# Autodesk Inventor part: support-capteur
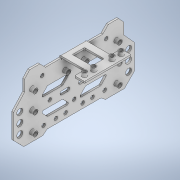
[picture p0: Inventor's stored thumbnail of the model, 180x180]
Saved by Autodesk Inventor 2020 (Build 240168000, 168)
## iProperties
Created: 2022-02
Part Number: support-capteur
Material: Générique
Document SubType Name: Modeling
Designer: bruno
Density: 1 g/cm^3
Appearance: Par défaut
Author: bruno
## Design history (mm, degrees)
sketch "Esquisse1"
  geometry: L1 (32.088, -75.124)-(29.483, 74.118); L2 (29.483, 74.118)-(111.566, 75.551); L3 (111.566, 75.551)-(114.171, -73.691); L4 (114.171, -73.691)-(32.088, -75.124); L5 (66.232, 46.839)-(46.199, 46.839); L6 (66.23, -52.161)-(46.2, -52.161); L7 (89.845, 25.399)-(89.845, 33.715); L8 (37.796, 38.782)-(37.796, 23.107); L9 (46.199, 46.839)-(37.796, 38.532); L10 (89.845, 25.399)-(85.193, 20.8); L11 (85.193, 20.8)-(85.193, -2.661); L12 (89.845, 33.715)-(85.193, 37.93); L13 (85.193, 37.93)-(76.064, 37.93); L14 (76.064, 37.93)-(66.232, 46.839); L15 (37.796, 23.107)-(40.701, 19.391); L16 (40.701, 19.391)-(40.701, -2.661); L17 (40.701, -2.661)-(50.092, -2.661); L18 (50.092, -2.661)-(85.193, -2.661); L19 (71.331, 18.786)-(71.331, 3.129); L20 (71.016, 19.515)-(66.917, 23.371); L21 (65.232, 7.141)-(65.232, 22.643); L22 (69.631, 2.414)-(65.532, 6.426); L23 (61.89, 7.414)-(61.89, 2.414); L24 (58.89, 7.414)-(58.89, 2.414); L25 (60.39, 17.308)-(60.39, 7.414); L26 (49.764, 19.515)-(53.863, 23.371); L27 (55.548, 7.141)-(55.548, 22.643); L28 (49.449, 18.786)-(49.449, 3.129); L29 (51.148, 2.414)-(55.247, 6.426); C1 r 1.5 at (80.628, 23.543); C2 r 2.5 at (64.046, 41.839); C3 r 2.5 at (56.046, 41.839); C4 r 2.5 at (48.046, 41.839); C5 r 1.5 at (60.39, 17.308); C6 r 1.5 at (44.701, 22.339); C7 r 1.5 at (44.701, 12.339); C8 r 1.5 at (44.701, 4.339); C9 r 1.5 at (60.39, 31.839); C10 r 1.5 at (75.4, 31.839); C11 r 1.5 at (44.89, 31.839); C12 r 1.5 at (75.193, 4.839); C13 r 1.5 at (50.831, -2.661); A1 r 1.5 centre (60.39, 7.414) between (61.89, 7.414) and (58.89, 7.414); A2 r 1 centre (70.331, 3.129) between (69.631, 2.414) and (71.331, 3.129); A3 r 1 centre (66.232, 7.141) between (65.232, 7.141) and (65.532, 6.426); A4 r 1 centre (66.232, 22.643) between (66.917, 23.371) and (65.232, 22.643); A5 r 1 centre (70.331, 18.786) between (71.331, 18.786) and (71.016, 19.515); A6 r 1.5 centre (60.39, 2.414) between (58.89, 2.414) and (61.89, 2.414); A7 r 1 centre (54.548, 22.643) between (55.548, 22.643) and (53.863, 23.371); A8 r 1 centre (50.449, 18.786) between (49.764, 19.515) and (49.449, 18.786); A9 r 1 centre (54.548, 7.141) between (55.247, 6.426) and (55.548, 7.141); A10 r 1 centre (50.449, 3.129) between (49.449, 3.129) and (51.148, 2.414); 3 further points; 1 other entity
  constraints: 50 end point, 23 centre point, 20 point on circle, 12 symmetric about line, 10 tangent, 6 vertical, 3 horizontal, 3 parallel, 2 equal radius, 2 point on line, 1 perpendicular, 6 other
  dimensions: "d5" = 99 distance between parallel lines of L6 L5; "d8" = 52.04902 distance between parallel lines of L7 L8; "d16" = 49.5 distance between parallel lines of L5 L17; "d17" = 1 radius of A2 (derived); "d19" = 1 radius of A5 (derived); "d20" = 5 diameter of C2; "d21" = 5 diameter of C3; "d22" = 5 diameter of C4; "d23" = 3 dimension on C4 C3; "d24" = 8 distance of C2.centre C3.centre; "d25" = 5 distance from line of C2.centre L5; "d26" = 5 distance from line of L5 C3.centre; "d27" = 7.5 dimension on C4 L5; "d28" = 3 diameter of C10; "d29" = 3 diameter of C9; "d30" = 3 diameter of C11; "d31" = 15 distance from line of L5 C9.centre; "d32" = 15 distance from line of L5 C11.centre; "d33" = 15 distance from line of L5 C10.centre; "d34" = 3 diameter of C6; "d35" = 3 diameter of C7; "d36" = 3 diameter of C8; "d37" = 24.5 distance from line of C6.centre L5; "d38" = 4 distance from line of L16 C6.centre; "d39" = 4 distance from line of L16 C7.centre; "d40" = 4 distance from line of L16 C8.centre; "d41" = 10 distance of C7.centre C6.centre; "d42" = 8 distance of C8.centre C7.centre; "d43" = 3 diameter of C1; "d44" = 10 distance from line of C12.centre L11; "d45" = 3 diameter of C12; "d46" = 27 vertical distance of C12.centre C10.centre; "d47" = 3 diameter of C5; "d48" = 3 diameter of A6; "d49" = 3 diameter of A1; "d50" = 5 distance of A6.centre L25.end; "d52" = 3 diameter of C13
extrude "Extrusion1" new body sketch "Esquisse1" distance "d53" = 1.5; taper "d54" = 0 deg
sketch "Esquisse2"
  geometry: C1 r 1.5 at (-31.839, 75.4) reference; C2 r 1.5 at (-31.839, 60.39) reference; C3 r 1.5 at (-31.839, 44.89) reference; C4 r 1.5 at (-4.839, 75.193) reference; C5 r 1.5 at (10.161, 75.193) reference; C6 r 1.5 at (37.161, 75.4) reference; C7 r 1.5 at (37.161, 60.39) reference; C8 r 1.5 at (37.161, 44.89) reference; C9 r 2 at (-31.839, 75.4); C10 r 1.5 at (-31.839, 60.39) reference; C11 r 2 at (-31.839, 60.39); C12 r 1.5 at (-31.839, 44.89) reference; C13 r 2 at (-31.839, 44.89); C14 r 1.5 at (-4.839, 75.193) reference; C15 r 2 at (-4.839, 75.193); 1 further point
  constraints: 4 centre point, 4 coincident
  dimensions: "d55" = 4 diameter of C9; "d56" = 4 diameter of C11; "d57" = 4 diameter of C13; "d58" = 4 diameter of C15
extrude "Extrusion2" join sketch "Esquisse2" distance "d59" = 3; taper "d60" = 0 deg
feature "Filetage1" dims "d61" = 4.5, "d62" = 0
feature "Filetage2" dims "d63" = 4.5, "d64" = 0
feature "Filetage3" dims "d65" = 4.5, "d66" = 0
feature "Filetage4" dims "d67" = 4.5, "d68" = 0
mirror "Symétrie2"
sketch "Esquisse3"
  geometry: L1 (0, 0)-(0, 46.922) reference; L2 (1.5, 0)-(1.5, 46.922) reference; L3 (0, 1.409)-(0, 45.513) reference; L4 (0, 12.961)-(20.5, 12.961); L5 (21, 12.961)-(21, 27.961); L6 (20.5, 33.961)-(0, 33.961); L7 (0, 33.961)-(0, 12.961); L8 (21.5, 4.461)-(28.5, 4.461); L9 (29, 4.961)-(29, 41.961); L10 (28.5, 42.461)-(21.5, 42.461); L11 (21, 12.461)-(21, 4.961); L12 (1.5, 1.409)-(1.5, 45.513) reference; L13 (1.5, 23.461)-(-9.009, 23.461); L14 (5.5, 18.461)-(20.5, 18.461); L15 (21, 18.961)-(21, 28.461); L16 (20.5, 28.461)-(5.5, 28.461); L17 (5, 27.961)-(5, 18.961); L18 (21, 41.961)-(21, 34.461); C1 r 1.5 at (25, 8.461); C2 r 1.5 at (25, 15.961); C3 r 1.5 at (25, 30.961); C4 r 1.5 at (25, 38.461); A1 r 0.5 centre (20.5, 12.461) between (21, 12.461) and (20.5, 12.961); A2 r 0.5 centre (5.5, 18.961) between (5, 18.961) and (5.5, 18.461); A3 r 0.5 centre (20.5, 18.961) between (20.5, 18.461) and (21, 18.961); A4 r 0.5 centre (20.5, 27.961) between (21, 27.961) and (20.5, 28.461); A5 r 0.5 centre (5.5, 27.961) between (5.5, 28.461) and (5, 27.961); A6 r 0.5 centre (20.5, 34.461) between (20.5, 33.961) and (21, 34.461); A7 r 0.5 centre (21.5, 41.961) between (21.5, 42.461) and (21, 41.961); A8 r 0.5 centre (28.5, 41.961) between (29, 41.961) and (28.5, 42.461); A9 r 0.5 centre (28.5, 4.961) between (28.5, 4.461) and (29, 4.961); A10 r 0.5 centre (21.5, 4.961) between (21, 4.961) and (21.5, 4.461); 10 further points
  constraints: 28 end point, 20 point on circle, 20 tangent, 18 point on line, 14 centre point, 8 equal radius, 6 parallel, 4 horizontal, 3 perpendicular, 2 symmetric about line, 1 midpoint, 1 vertical, 2 other
  dimensions: "d69" = 21 distance of L6.end point (21, 33.961); "d70" = 21 distance of point (21, 33.961) L5.start; "d71" = 8 distance of point (21, 42.461) point (29, 42.461); "d72" = 38 distance of point (29, 42.461) point (29, 4.461); "d73" = 10.5 distance between parallel lines of L6 L13; "d74" = 19 distance between parallel lines of L8 L13; "d75" = 10 distance between parallel lines of L16 L14; "d76" = 16 distance of point (5, 18.461) point (21, 18.461); "d77" = 5 distance between parallel lines of L13 L14; "d78" = 5 distance between parallel lines of L7 L17; "d79" = 0.5 radius of A1; "d80" = 0.5 radius of A6 (derived); "d81" = 3 diameter of C1; "d82" = 3 diameter of C2; "d83" = 7.5 distance from line of C2.centre L13; "d84" = 15 distance from line of L13 C1.centre
extrude "Extrusion3" join sketch "Esquisse3" distance "d85" = 1.5; taper "d86" = 0 deg
fillet "Congé1" dims "d87" = 1
sketch "Esquisse4"
  geometry: C1 r 1.5 at (25, 8.461) reference; C2 r 1.5 at (25, 15.961) reference; C3 r 1.5 at (25, 30.961) reference; C4 r 1.5 at (25, 38.461) reference; C5 r 2 at (25, 8.461); C6 r 1.5 at (25, 15.961) reference; C7 r 2 at (25, 15.961); C8 r 1.5 at (25, 30.961) reference; C9 r 2 at (25, 30.961); C10 r 2 at (25, 38.461); 1 further point
  constraints: 4 centre point, 4 coincident
  dimensions: "d88" = 4 diameter of C5; "d89" = 4 diameter of C7; "d90" = 4 diameter of C9; "d91" = 4 diameter of C10
extrude "Extrusion4" join sketch "Esquisse4" distance "d92" = 3; taper "d93" = 0 deg
feature "Filetage5" dims "d94" = 4.5, "d95" = 0
feature "Filetage6" dims "d96" = 4.5, "d97" = 0
feature "Filetage7" dims "d98" = 4.5, "d99" = 0
feature "Filetage8" dims "d100" = 4.5, "d101" = 0
node "Solide1"
node "Image1"
